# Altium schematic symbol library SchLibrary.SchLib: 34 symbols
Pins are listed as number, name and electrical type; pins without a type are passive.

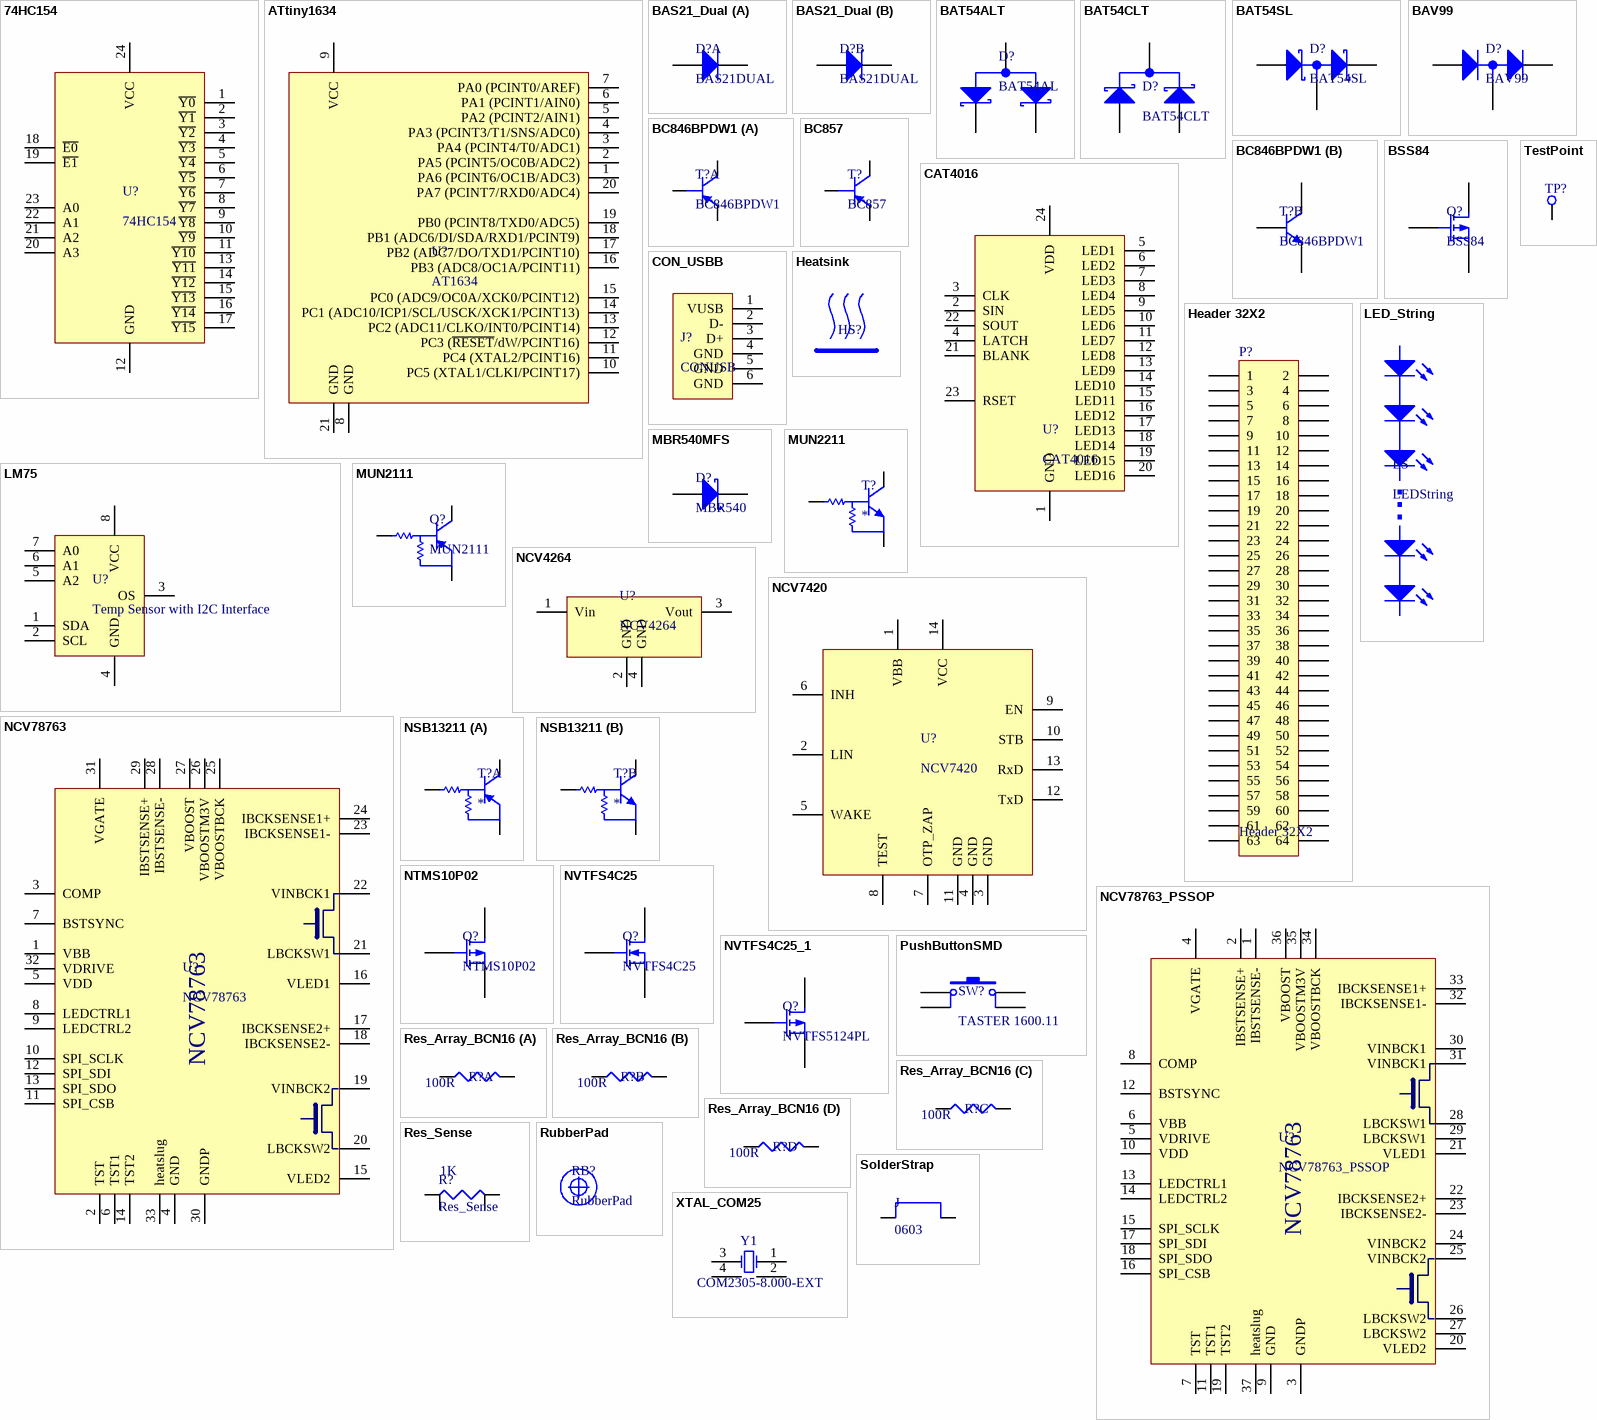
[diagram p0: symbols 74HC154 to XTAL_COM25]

## 74HC154
designator U?
footprint SOIC-24_W (SOIC, 24-Leads, Body 15,30x7,47mm, Pitch 1,27mm, IPC Medium Density)
pins: 1 ~{Y0}, 2 ~{Y1}, 3 ~{Y2}, 4 ~{Y3}, 5 ~{Y4}, 6 ~{Y5}, 7 ~{Y6}, 8 ~{Y7}, 9 ~{Y8}, 10 ~{Y9}, 11 ~{Y10}, 12 GND, 13 ~{Y11}, 14 ~{Y12}, 15 ~{Y13}, 16 ~{Y14}, 17 ~{Y15}, 18 ~{E0}, 19 ~{E1}, 20 A3, 21 A2, 22 A1, 23 A0, 24 VCC

## ATtiny1634
designator U?, comment AT1634
footprint 20M1_N (QFN, 20-Leads, Body 4x4mm, Pitch 0.5mm, IPC Medium Density)
pins: 1 PA6 (PCINT6/OC1B/ADC3), 2 PA5 (PCINT5/OC0B/ADC2), 3 PA4 (PCINT4/T0/ADC1), 4 PA3 (PCINT3/T1/SNS/ADC0), 5 PA2 (PCINT2/AIN1), 6 PA1 (PCINT1/AIN0), 7 PA0 (PCINT0/AREF), 8 GND, 9 VCC, 10 PC5 (XTAL1/CLKI/PCINT17), 11 PC4 (XTAL2/PCINT16), 12 PC3 (~{RESET}/dW/PCINT16), 13 PC2 (ADC11/CLKO/INT0/PCINT14), 14 PC1 (ADC10/ICP1/SCL/USCK/XCK1/PCINT13), 15 PC0 (ADC9/OC0A/XCK0/PCINT12), 16 PB3 (ADC8/OC1A/PCINT11), 17 PB2 (ADC7/DO/TXD1/PCINT10), 18 PB1 (ADC6/DI/SDA/RXD1/PCINT9), 19 PB0 (PCINT8/TXD0/ADC5), 20 PA7 (PCINT7/RXD0/ADC4), 21 GND

## BAS21_Dual
designator D?, comment BAS21DUAL
footprint SC-88A (SOT353, 5-Leads, Body 2x1.3mm, Pitch 0.65mm, Lead Span 2.1mm, IPC Medium Density)
part A pins: 1 A, 5 K
part B pins: 3 A, 4 K

## BAT54ALT
designator D?, comment BAT54AL
footprint SOT23 (SOT23, 3-Leads, Body 2.90x2.37mm, Pitch 0.95mm, IPC Medium Density)
pins: 1 A, 2 K, 3 A/K

## BAT54CLT
designator D?
footprint SOT23 (SOT23, 3-Leads, Body 2.90x2.37mm, Pitch 0.95mm, IPC Medium Density)
pins: 1 A, 2 K, 3 A/K

## BAT54SL
designator D?
footprint SOT23 (SOT23, 3-Leads, Body 2.90x2.37mm, Pitch 0.95mm, IPC Medium Density)
pins: 1 A, 2 K, 3 A/K

## BAV99
designator D?
footprint SOT23 (SOT23, 3-Leads, Body 2.90x2.37mm, Pitch 0.95mm, IPC Medium Density)
pins: 1 A, 2 K, 3 A/K

## BC846BPDW1
designator T?
footprint SOT-363
part A pins: 3 PNP_C, 4 PNP_E, 5 PNP_B
part B pins: 1 NPN_E, 2 NPN_B, 6 NPN_C

## BC857
designator T?
footprint SOT23 (SOT23, 3-Leads, Body 2.90x2.37mm, Pitch 0.95mm, IPC Medium Density)
simulation model Qbc856alt1g (Model Description)
pins: 1 B, 2 E, 3 C

## BSS84
designator Q?
simulation model bss84lt1 (Model Description)
footprint SOT23 (SOT23, 3-Leads, Body 2.90x2.37mm, Pitch 0.95mm, IPC Medium Density)
pins: 1 G, 2 S, 3 D

## CAT4016
designator U?
16channel LED driver - constant current
footprint SOIC-24_W (SOIC, 24-Leads, Body 15,30x7,47mm, Pitch 1,27mm, IPC Medium Density)
pins: 1 GND, 2 SIN, 3 CLK, 4 LATCH, 5 LED1, 6 LED2, 7 LED3, 8 LED4, 9 LED5, 10 LED6, 11 LED7, 12 LED8, 13 LED9, 14 LED10, 15 LED11, 16 LED12, 17 LED13, 18 LED14, 19 LED15, 20 LED16, 21 BLANK, 22 SOUT, 23 RSET, 24 VDD

## CON_USBB
designator J?, comment CONUSB
footprint CON_USBB
pins: 1 VUSB, 2 D-, 3 D+, 4 GND, 5 GND, 6 GND

## Header 32X2
designator P?
Header, 32-Pin, Dual row
footprint HDR2X32_1MM (Connector; Header; 30x2 Position)
pins: 1, 2, 3, 4, 5, 6, 7, 8, 9, 10, 11, 12, 13, 14, 15, 16, 17, 18, 19, 20, 21, 22, 23, 24, 25, 26, 27, 28, 29, 30, 31, 32, 33, 34, 35, 36, 37, 38, 39, 40, 41, 42, 43, 44, 45, 46, 47, 48, 49, 50, 51, 52, 53, 54, 55, 56, 57, 58, 59, 60, 61, 62, 63, 64

## Heatsink
designator HS?  (value not drawn)  (mechanical)
Heatsink

## LED_String
designator LS, comment LEDString  (mechanical)

## LM75
designator U?, comment Temp Sensor with I2C Interface
footprint SOIC-8 (8-Pin Small Outline Integrated Circuit 1.27 mm Pitch, IPC Medium Density)
pins: 1 SDA, 2 SCL, 3 OS, 4 GND, 5 A2, 6 A1, 7 A0, 8 VCC

## MBR540MFS
designator D?, comment MBR540
footprint SO8FL_3pin
simulation model Dmbr540mfs (Model Description)
pins: 1 A, 3 K

## MUN2111
designator Q?
footprint SOT23 (SOT23, 3-Leads, Body 2.90x2.37mm, Pitch 0.95mm, IPC Medium Density)
simulation model mun2111t1 (Model Description)
pins: 1 B, 2 E, 3 C

## MUN2211
designator T?
footprint SOT23 (SOT23, 3-Leads, Body 2.90x2.37mm, Pitch 0.95mm, IPC Medium Density)
simulation model mun2211t1
pins: 1 B, 2 E, 3 C

## NCV4264
designator U?
footprint SOT223_N (SOT223, 4-Leads, Body 6.5x3.5mm, Pitch 2.3mm, Lead Span 7mm, IPC Medium Density)
pins: 1 Vin, 2 GND, 3 Vout, 4 GND

## NCV7420
designator U?
footprint SOIC-14 (14-Pin Small Outline Integrated Circuit 1.27 mm Pitch, IPC Medium Density)
pins: 1 VBB, 2 LIN, 3 GND, 4 GND, 5 WAKE, 6 INH, 7 OTP_ZAP, 8 TEST, 9 EN, 10 STB, 11 GND, 12 TxD, 13 RxD, 14 VCC

## NCV78763
designator U?
NCV78763 Power Ballast and Dual LED Driver for Automotive Front Lighting
footprint QFN32_0_5MM (QFN, 32-Leads, Body 5x5mm, Pitch 0.5mm, IPC Medium Density)
pins: 1 VBB, 2 TST, 3 COMP, 4 GND, 5 VDD, 6 TST1, 7 BSTSYNC, 8 LEDCTRL1, 9 LEDCTRL2, 10 SPI_SCLK, 11 SPI_CSB, 12 SPI_SDI, 13 SPI_SDO, 14 TST2, 15 VLED2, 16 VLED1, 17 IBCKSENSE2+, 18 IBCKSENSE2-, 19 VINBCK2, 20 LBCKSW2, 21 LBCKSW1, 22 VINBCK1, 23 IBCKSENSE1-, 24 IBCKSENSE1+, 25 VBOOSTBCK, 26 VBOOSTM3V, 27 VBOOST, 28 IBSTSENSE-, 29 IBSTSENSE+, 30 GNDP, 31 VGATE, 32 VDRIVE, 33 heatslug

## NCV78763_PSSOP
designator U?
NCV78763 Power Ballast and Dual LED Driver for Automotive Front Lighting
footprint SSOP50P1030X265_HS-37N (SSOP, 36-Leads, Body 10.30x7.50mm, Pitch 0.50mm, Thermal Pad 5.90.2x4.10.2mm, IPC Medium Density)
pins: 1 IBSTSENSE-, 2 IBSTSENSE+, 3 GNDP, 4 VGATE, 5 VDRIVE, 6 VBB, 7 TST, 8 COMP, 9 GND, 10 VDD, 11 TST1, 12 BSTSYNC, 13 LEDCTRL1, 14 LEDCTRL2, 15 SPI_SCLK, 16 SPI_CSB, 17 SPI_SDI, 18 SPI_SDO, 19 TST2, 20 VLED2, 21 VLED1, 22 IBCKSENSE2+, 23 IBCKSENSE2-, 24 VINBCK2, 25 VINBCK2, 26 LBCKSW2, 27 LBCKSW2, 28 LBCKSW1, 29 LBCKSW1, 30 VINBCK1, 31 VINBCK1, 32 IBCKSENSE1-, 33 IBCKSENSE1+, 34 VBOOSTBCK, 35 VBOOSTM3V, 36 VBOOST, 37 heatslug

## NSB13211
designator T?
footprint SOT-363
part A pins: 3 C1, 4 E1, 5 B1
part B pins: 1 E, 2 B, 6 C

## NTMS10P02
designator Q?
P-Channel MOSFET SO8
footprint SOIC-8 (8-Pin Small Outline Integrated Circuit 1.27 mm Pitch, IPC Medium Density)
pins: 1 S, 2 S, 3 S, 4 G, 5 D, 6 D, 7 D, 8 D

## NVTFS4C25
designator Q?
simulation model nttfs4c25n (Model Description)
footprint U8FL
pins: D, G, S

## NVTFS4C25_1
designator Q?, comment NVTFS5124PL
P-Channel MOSFET u8FL
footprint U8FL
pins: 1 S, 2 G, 3 D

## PushButtonSMD
designator SW?, comment TASTER 1600.11
footprint PUSHBUTTON_SMD
pins: 1, 2, 3, 4

## Res_Array_BCN16
designator R?  value 100R  (hidden comment: Res_Array_BCN16)
Resistor
footprint BCN16
part A pins: 1, 8 2
part B pins: 2 1, 7 2
part C pins: 3 1, 6 2
part D pins: 4 1, 5 2

## Res_Sense
designator R?  value 1K
Resistor
simulation model RESISTOR (Resistor)
footprint 1206_RSENSE (Chip Capacitor, Body 3.2x1.6mm, IPC High Density)
pins: 1, 2, 3, 4

## RubberPad
designator RB?  (mechanical)

## SolderStrap
designator J, comment 0603
Resistor; Value: 1K
footprint SolderStrap (Solder Strap)
pins: 1, 2

## TestPoint
designator TP?, comment TP  (value not drawn)
footprint TP_1mm (Testpoint DIA 1mm)
pins: 1 TP

## XTAL_COM25
designator Y1, comment COM2305-8.000-EXT
Crystal Oscillator
footprint XTAL_COM25
footprint XTAL_MQ
pins: 1 OSC1, 2 GND1, 3 OSC2, 4 GND2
